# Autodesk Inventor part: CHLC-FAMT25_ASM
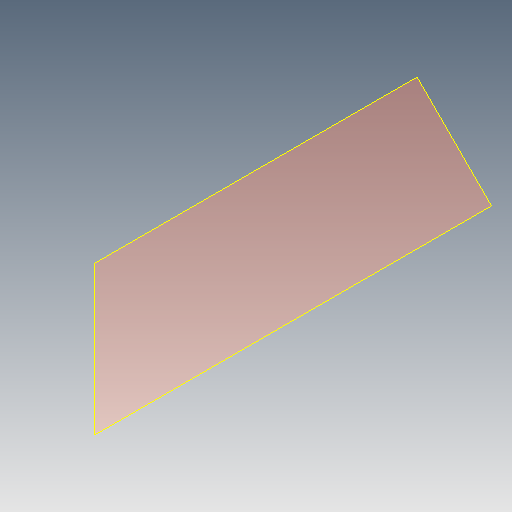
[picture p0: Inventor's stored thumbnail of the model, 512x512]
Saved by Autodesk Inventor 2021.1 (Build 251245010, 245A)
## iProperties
Created: 2021-05
Part Number: CHLC-FAMT25_ASM
Material: Ogólny
Document SubType Name: Modeling
Designer: user
Density: 1 g/cm^3
Appearance: Domyślna
Author: user
Revision Number: ÈÎºÎ
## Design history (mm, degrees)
feature "Złożony1"
body "Srf1"
